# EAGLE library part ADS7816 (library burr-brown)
12-Bit High Speed Micro Power Sampling ADC
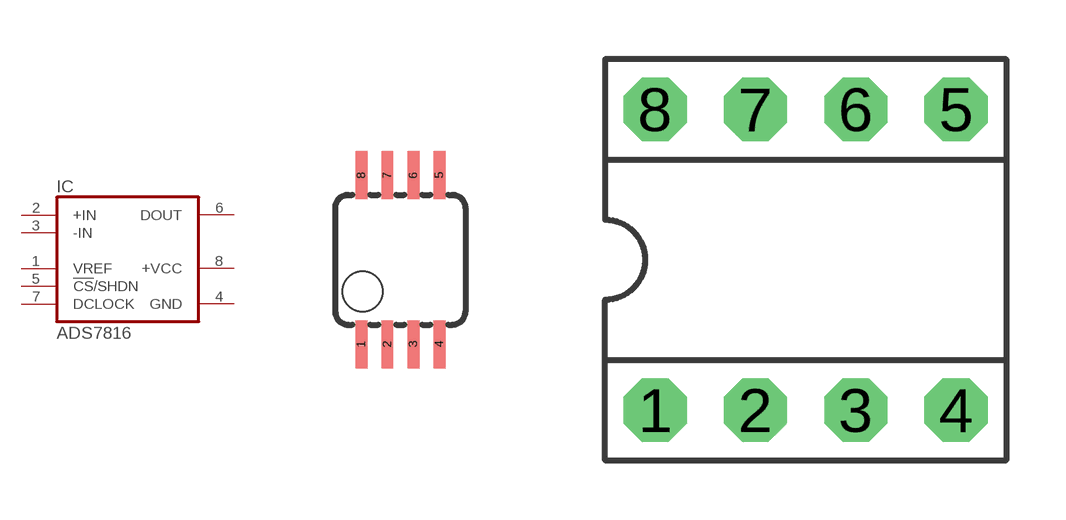
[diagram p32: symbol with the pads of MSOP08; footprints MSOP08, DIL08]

Designator prefix IC

## ADS7816E (MF: TEXAS INSTRUMENT CONNECTORS; MPN: ADS7816EC/250; OC_FARNELL: 1754724; OC_NEWARK: 74C7108)  [MSOP08]
1  VREF  in
2  +IN  in
3  -IN  in
4  GND  pwr
5  !CS!/SHDN  in
6  DOUT  out
7  DCLOCK  in
8  +VCC  pwr

## ADS7816P (MF: TEXAS INSTRUMENT CONNECTORS; MPN: ADS7816P; OC_FARNELL: 1097576; OC_NEWARK: 14M9332)  [DIL08]
Pads as for MSOP08

## ADS7816U (MF: TEXAS INSTRUMENTS; MPN: ADS7816U; OC_FARNELL: 1273124; OC_NEWARK: 80K5554)  [SO08-GW]
Pads as for MSOP08

## Footprint MSOP08 (pad centres in mm)
Mini Small Outline Package
smd 0.3 x 1.2: 1 -0.976,-2.113; 2 -0.326,-2.113; 3 0.324,-2.113; 4 0.974,-2.113; 5 0.974,2.112; 6 0.324,2.112; 7 -0.326,2.112; 8 -0.976,2.112

## Footprint DIL08 (pad centres in mm)
Dual In Line
drill 0.813 pad 1.6 octagon: 1 -3.81,-3.81; 2 -1.27,-3.81; 3 1.27,-3.81; 4 3.81,-3.81; 5 3.81,3.81; 6 1.27,3.81; 7 -1.27,3.81; 8 -3.81,3.81

## Footprint SO08-GW (pad centres in mm)
Small Outline Package, gull wing
smd 0.762 x 2.21: 1 -3.81,-4.318; 2 -1.27,-4.318; 3 1.27,-4.318; 4 3.81,-4.318; 5 3.81,4.318; 6 1.27,4.318; 7 -1.27,4.318; 8 -3.81,4.318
